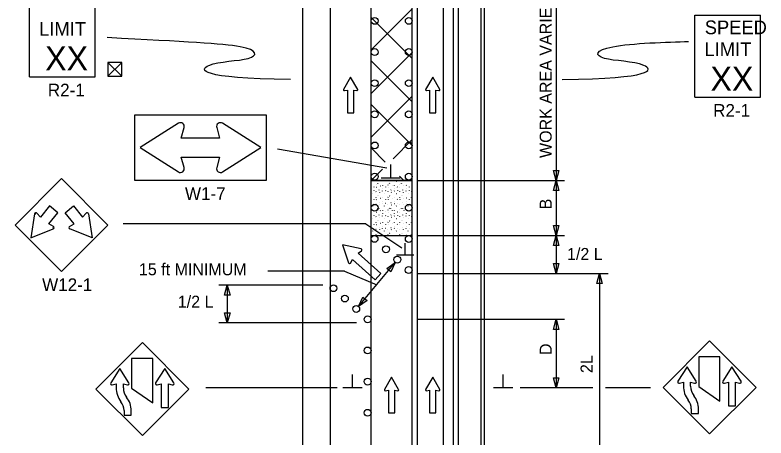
# Model space of a CAD drawing. Extents: x 16480 to 18482, y 7002 to 8333.
# Drawn here: x 16745.9 to 17184.5, y 7872.3 to 8119.6 of the extents above; entities that cross this region are included whole.
import ezdxf

# ---------------------------------------------------------------- set-up
doc = ezdxf.new("R2010")
doc.units = 0
for name, color, linetype in [('ALI_LEGAL_EX', 7, 'Continuous'), ('MT_SCRATCH_LEVEL_E', 7, 'Continuous'), ('PAVT_EDGE_EX', 7, 'Continuous'), ('TRAFFIC_SIGNS_PR', 7, 'Continuous'), ('TYPICAL_TEXT_DIMEN_PR', 7, 'Continuous')]:
    doc.layers.add(name, color=color, linetype=linetype)

msp = doc.modelspace()

# ---------------------------------------------------------------- linework, layer by layer
at = {"layer": 'ALI_LEGAL_EX'}
for p, q in [((16980.68, 8333.08), (16980.68, 7514.94)), ((17004.68, 8333.08), (17004.68, 7514.94)), ((16995.95, 8289.26), (16995.95, 7471.12)), ((17019.95, 8289.26), (17019.95, 7471.12)), ((16953.87, 7620.35), (16953.87, 8241.48)), ((16977.87, 7620.35), (16977.87, 8241.48))]:
    msp.add_line(p, q, dxfattribs=at)
for points in [[(16953.87, 8075.35), (16953.87, 8100.35)], [(16977.87, 8075.35), (16977.87, 8100.35)], [(16953.87, 7875.35), (16953.87, 7900.35)], [(16977.87, 7875.35), (16977.87, 7900.35)]]:
    msp.add_lwpolyline(points, dxfattribs=at)
at = {"layer": 'MT_SCRATCH_LEVEL_E'}
for p, q in [((16941.87, 8083.36), (16937.75, 8076.12)), ((16946.01, 8076.12), (16941.87, 8083.36)), ((16989.82, 8083.36), (16985.71, 8076.12)), ((16993.97, 8076.12), (16989.82, 8083.36)), ((16938.24, 8075.44), (16940.01, 8075.75)), ((16940.01, 8075.75), (16940.01, 8062.5)), ((16943.76, 8062.5), (16943.76, 8075.75)), ((16943.76, 8075.75), (16945.53, 8075.44)), ((16986.19, 8075.44), (16987.97, 8075.75)), ((16987.97, 8075.75), (16987.97, 8062.5)), ((16991.71, 8062.5), (16991.71, 8075.75)), ((16991.71, 8075.75), (16993.49, 8075.44)), ((16940.01, 8062.5), (16943.76, 8062.5)), ((16987.97, 8062.5), (16991.71, 8062.5)), ((16948, 7982.89), (16937.12, 7985.21)), ((16937.12, 7985.21), (16940.66, 7974.69)), ((16946.36, 7980.32), (16948.25, 7981.81)), ((16959.53, 7968.53), (16946.36, 7980.32)), ((16941.76, 7974.56), (16943.03, 7976.61)), ((16943.03, 7976.61), (16956.2, 7964.82)), ((16956.2, 7964.82), (16959.53, 7968.53)), ((16965.77, 7907.86), (16961.66, 7900.61)), ((16969.92, 7900.61), (16965.77, 7907.86)), ((16989.82, 7907.86), (16985.71, 7900.61)), ((16993.97, 7900.61), (16989.82, 7907.86)), ((16962.14, 7899.93), (16963.92, 7900.24)), ((16963.92, 7900.24), (16963.92, 7886.99)), ((16967.66, 7886.99), (16967.66, 7900.24)), ((16967.66, 7900.24), (16969.44, 7899.93)), ((16986.19, 7899.93), (16987.97, 7900.24)), ((16987.97, 7900.24), (16987.97, 7886.99)), ((16991.71, 7886.99), (16991.71, 7900.24)), ((16991.71, 7900.24), (16993.49, 7899.93)), ((16963.92, 7886.99), (16967.66, 7886.99)), ((16987.97, 7886.99), (16991.71, 7886.99))]:
    msp.add_line(p, q, dxfattribs=at)
for centre, radius, start, end in [((16938.16, 8075.9), 0.463, 150.4248, 279.9638), ((16945.6, 8075.9), 0.463, 260.0362, 29.7731), ((16986.12, 8075.9), 0.463, 150.4248, 279.9638), ((16993.56, 8075.9), 0.463, 260.0362, 29.7731), ((16947.86, 7982.29), 0.617, 308.2002, 77.9371), ((16941.24, 7974.9), 0.617, 198.5889, 328.1278), ((16962.07, 7900.39), 0.463, 150.4248, 279.9638), ((16969.51, 7900.39), 0.463, 260.0362, 29.7731), ((16986.12, 7900.39), 0.463, 150.4248, 279.9638), ((16993.56, 7900.39), 0.463, 260.0362, 29.7731)]:
    msp.add_arc(centre, radius, start, end, dxfattribs=at)
at = {"layer": 'PAVT_EDGE_EX'}
for p, q in [((16913.87, 8212.75), (16913.87, 7461.39)), ((16929.87, 8212.75), (16929.87, 7461.39)), ((17001.87, 8212.75), (17001.87, 7461.39)), ((17017.87, 8212.75), (17017.87, 7461.39)), ((16953.87, 8099.17), (16977.87, 8123.17)), ((16977.87, 8094.26), (16953.87, 8118.26)), ((16953.87, 8073.71), (16977.87, 8097.71)), ((16977.87, 8068.81), (16953.87, 8092.81)), ((16953.87, 8048.26), (16977.87, 8072.26)), ((16977.87, 8043.35), (16953.87, 8067.35)), ((16966.65, 8035.59), (16977.87, 8046.8)), ((16962.09, 8033.67), (16953.87, 8041.89)), ((16953.87, 8022.8), (16960.46, 8029.4)), ((16953.87, 8022.8), (16977.87, 8022.8)), ((16953.87, 8022.8), (16977.87, 8022.8)), ((16977.87, 8022.8), (16953.87, 8022.8)), ((16953.87, 8022.8), (16953.87, 8022.8)), ((16954.79, 8022.44), (16954.85, 8022.56)), ((16961.68, 8022.44), (16961.73, 8022.56)), ((16968.57, 8022.44), (16968.62, 8022.56)), ((16972.96, 8022.8), (16970.42, 8025.34)), ((16975.46, 8022.44), (16975.51, 8022.56)), ((16955.36, 8019.12), (16955.42, 8019.04)), ((16956.81, 8020.25), (16956.87, 8020.36)), ((16956.89, 8018.98), (16956.94, 8018.9)), ((16957.58, 8021.21), (16957.63, 8021.13)), ((16958.31, 8021.18), (16958.37, 8021.1)), ((16959.18, 8019.8), (16959.24, 8019.72)), ((16960.46, 8018.06), (16960.51, 8017.98)), ((16960.63, 8019.95), (16960.68, 8020.07)), ((16962.25, 8019.12), (16962.3, 8019.04)), ((16963.7, 8020.25), (16963.75, 8020.36)), ((16963.78, 8018.98), (16963.83, 8018.9)), ((16964.47, 8021.21), (16964.52, 8021.13)), ((16965.2, 8021.18), (16965.25, 8021.1)), ((16966.07, 8019.8), (16966.12, 8019.72)), ((16967.35, 8018.06), (16967.4, 8017.98)), ((16967.52, 8019.95), (16967.57, 8020.07)), ((16969.14, 8019.12), (16969.19, 8019.04)), ((16970.59, 8020.25), (16970.64, 8020.36)), ((16970.67, 8018.98), (16970.72, 8018.9)), ((16971.35, 8021.21), (16971.4, 8021.13)), ((16972.09, 8021.18), (16972.14, 8021.1)), ((16972.96, 8019.8), (16973.01, 8019.72)), ((16974.24, 8018.06), (16974.29, 8017.98)), ((16974.41, 8019.95), (16974.46, 8020.07)), ((16976.03, 8019.12), (16976.08, 8019.04)), ((16977.48, 8020.25), (16977.53, 8020.36)), ((16977.56, 8018.98), (16977.61, 8018.9)), ((16954.79, 8015.16), (16954.85, 8015.28)), ((16955.41, 8016.91), (16955.46, 8016.83)), ((16956.69, 8016.34), (16956.71, 8016.22)), ((16957.58, 8013.92), (16957.63, 8013.85)), ((16958.31, 8013.89), (16958.37, 8013.82)), ((16958.53, 8017.19), (16958.59, 8017.31)), ((16958.72, 8015.99), (16958.78, 8015.91)), ((16960.5, 8016.66), (16960.55, 8016.78)), ((16961.68, 8015.16), (16961.73, 8015.28)), ((16962.3, 8016.91), (16962.35, 8016.83)), ((16963.58, 8016.34), (16963.59, 8016.22)), ((16964.47, 8013.92), (16964.52, 8013.85)), ((16965.2, 8013.89), (16965.25, 8013.82)), ((16965.42, 8017.19), (16965.47, 8017.31)), ((16965.61, 8015.99), (16965.66, 8015.91)), ((16967.39, 8016.66), (16967.44, 8016.78)), ((16968.57, 8015.16), (16968.62, 8015.28)), ((16969.19, 8016.91), (16969.24, 8016.83)), ((16970.47, 8016.34), (16970.48, 8016.22)), ((16971.35, 8013.92), (16971.4, 8013.85)), ((16972.09, 8013.89), (16972.14, 8013.82)), ((16972.31, 8017.19), (16972.36, 8017.31)), ((16972.5, 8015.99), (16972.55, 8015.91)), ((16974.28, 8016.66), (16974.33, 8016.78)), ((16975.46, 8015.16), (16975.51, 8015.28)), ((16976.07, 8016.91), (16976.13, 8016.83)), ((16977.36, 8016.34), (16977.37, 8016.22)), ((16955.36, 8011.84), (16955.42, 8011.76)), ((16955.41, 8009.63), (16955.46, 8009.55)), ((16956.69, 8009.05), (16956.71, 8008.93)), ((16956.81, 8012.96), (16956.87, 8013.08)), ((16956.89, 8011.7), (16956.94, 8011.62)), ((16958.53, 8009.91), (16958.59, 8010.02)), ((16959.18, 8012.51), (16959.24, 8012.44)), ((16960.46, 8010.78), (16960.51, 8010.7)), ((16960.5, 8009.38), (16960.55, 8009.49)), ((16960.63, 8012.66), (16960.68, 8012.78)), ((16962.25, 8011.84), (16962.3, 8011.76)), ((16962.3, 8009.63), (16962.35, 8009.55)), ((16963.58, 8009.05), (16963.59, 8008.93)), ((16963.7, 8012.96), (16963.75, 8013.08)), ((16963.78, 8011.7), (16963.83, 8011.62)), ((16965.42, 8009.91), (16965.47, 8010.02)), ((16966.07, 8012.51), (16966.12, 8012.44)), ((16967.35, 8010.78), (16967.4, 8010.7)), ((16967.39, 8009.38), (16967.44, 8009.49)), ((16967.52, 8012.66), (16967.57, 8012.78)), ((16969.14, 8011.84), (16969.19, 8011.76)), ((16969.19, 8009.63), (16969.24, 8009.55)), ((16970.47, 8009.05), (16970.48, 8008.93)), ((16970.59, 8012.96), (16970.64, 8013.08)), ((16970.67, 8011.7), (16970.72, 8011.62)), ((16972.31, 8009.91), (16972.36, 8010.02)), ((16972.96, 8012.51), (16973.01, 8012.44)), ((16974.24, 8010.78), (16974.29, 8010.7)), ((16974.28, 8009.38), (16974.33, 8009.49)), ((16974.41, 8012.66), (16974.46, 8012.78)), ((16976.03, 8011.84), (16976.08, 8011.76)), ((16976.07, 8009.63), (16976.13, 8009.55)), ((16977.36, 8009.05), (16977.37, 8008.93)), ((16977.48, 8012.96), (16977.53, 8013.08)), ((16977.56, 8011.7), (16977.61, 8011.62)), ((16954.79, 8007.87), (16954.85, 8007.99)), ((16956.81, 8005.68), (16956.87, 8005.79)), ((16957.58, 8006.64), (16957.63, 8006.56)), ((16958.31, 8006.61), (16958.37, 8006.53)), ((16958.72, 8008.71), (16958.78, 8008.63)), ((16959.18, 8005.23), (16959.24, 8005.15)), ((16960.63, 8005.38), (16960.68, 8005.5)), ((16961.68, 8007.87), (16961.73, 8007.99)), ((16963.7, 8005.68), (16963.75, 8005.79)), ((16964.47, 8006.64), (16964.52, 8006.56)), ((16965.2, 8006.61), (16965.25, 8006.53)), ((16965.61, 8008.71), (16965.66, 8008.63)), ((16966.07, 8005.23), (16966.12, 8005.15)), ((16967.52, 8005.38), (16967.57, 8005.5)), ((16968.57, 8007.87), (16968.62, 8007.99)), ((16970.59, 8005.68), (16970.64, 8005.79)), ((16971.35, 8006.64), (16971.4, 8006.56)), ((16972.09, 8006.61), (16972.14, 8006.53)), ((16972.5, 8008.71), (16972.55, 8008.63)), ((16972.96, 8005.23), (16973.01, 8005.15)), ((16974.41, 8005.38), (16974.46, 8005.5)), ((16975.46, 8007.87), (16975.51, 8007.99)), ((16977.48, 8005.68), (16977.53, 8005.79)), ((16954.79, 8000.59), (16954.85, 8000.71)), ((16955.36, 8004.55), (16955.42, 8004.47)), ((16955.41, 8002.34), (16955.46, 8002.26)), ((16956.69, 8001.77), (16956.71, 8001.65)), ((16956.89, 8004.41), (16956.94, 8004.33)), ((16958.53, 8002.62), (16958.59, 8002.74)), ((16958.72, 8001.42), (16958.78, 8001.35)), ((16960.46, 8003.49), (16960.51, 8003.41)), ((16960.5, 8002.09), (16960.55, 8002.21)), ((16961.68, 8000.59), (16961.73, 8000.71)), ((16962.25, 8004.55), (16962.3, 8004.47)), ((16962.3, 8002.34), (16962.35, 8002.26)), ((16963.58, 8001.77), (16963.59, 8001.65)), ((16963.78, 8004.41), (16963.83, 8004.33)), ((16965.42, 8002.62), (16965.47, 8002.74)), ((16965.61, 8001.42), (16965.66, 8001.35)), ((16967.35, 8003.49), (16967.4, 8003.41)), ((16967.39, 8002.09), (16967.44, 8002.21)), ((16968.57, 8000.59), (16968.62, 8000.71)), ((16969.14, 8004.55), (16969.19, 8004.47)), ((16969.19, 8002.34), (16969.24, 8002.26)), ((16970.47, 8001.77), (16970.48, 8001.65)), ((16970.67, 8004.41), (16970.72, 8004.33)), ((16972.31, 8002.62), (16972.36, 8002.74)), ((16972.5, 8001.42), (16972.55, 8001.35)), ((16974.24, 8003.49), (16974.29, 8003.41)), ((16974.28, 8002.09), (16974.33, 8002.21)), ((16975.46, 8000.59), (16975.51, 8000.71)), ((16976.03, 8004.55), (16976.08, 8004.47)), ((16976.07, 8002.34), (16976.13, 8002.26)), ((16977.36, 8001.77), (16977.37, 8001.65)), ((16977.56, 8004.41), (16977.61, 8004.33)), ((16955.36, 7997.27), (16955.42, 7997.19)), ((16956.81, 7998.39), (16956.87, 7998.51)), ((16956.89, 7997.13), (16956.94, 7997.05)), ((16957.58, 7999.35), (16957.63, 7999.28)), ((16958.31, 7999.32), (16958.37, 7999.24)), ((16959.18, 7997.94), (16959.24, 7997.87)), ((16960.46, 7996.21), (16960.51, 7996.13)), ((16960.63, 7998.1), (16960.68, 7998.21)), ((16962.25, 7997.27), (16962.3, 7997.19)), ((16963.7, 7998.39), (16963.75, 7998.51)), ((16963.78, 7997.13), (16963.83, 7997.05)), ((16964.47, 7999.35), (16964.52, 7999.28)), ((16965.2, 7999.32), (16965.25, 7999.24)), ((16966.07, 7997.94), (16966.12, 7997.87)), ((16967.35, 7996.21), (16967.4, 7996.13)), ((16967.52, 7998.1), (16967.57, 7998.21)), ((16969.14, 7997.27), (16969.19, 7997.19)), ((16970.59, 7998.39), (16970.64, 7998.51)), ((16970.67, 7997.13), (16970.72, 7997.05)), ((16971.35, 7999.35), (16971.4, 7999.28)), ((16972.09, 7999.32), (16972.14, 7999.24)), ((16972.96, 7997.94), (16973.01, 7997.87)), ((16974.24, 7996.21), (16974.29, 7996.13)), ((16974.41, 7998.1), (16974.46, 7998.21)), ((16976.03, 7997.27), (16976.08, 7997.19)), ((16977.48, 7998.39), (16977.53, 7998.51)), ((16977.56, 7997.13), (16977.61, 7997.05)), ((16954.79, 7993.3), (16954.85, 7993.42)), ((16955.41, 7995.06), (16955.46, 7994.98)), ((16956.69, 7994.48), (16956.71, 7994.36)), ((16957.58, 7992.07), (16957.63, 7991.99)), ((16958.31, 7992.04), (16958.37, 7991.96)), ((16958.53, 7995.34), (16958.59, 7995.45)), ((16958.72, 7994.14), (16958.78, 7994.06)), ((16960.5, 7994.81), (16960.55, 7994.92)), ((16961.68, 7993.3), (16961.73, 7993.42)), ((16962.3, 7995.06), (16962.35, 7994.98)), ((16963.58, 7994.48), (16963.59, 7994.36)), ((16964.47, 7992.07), (16964.52, 7991.99)), ((16965.2, 7992.04), (16965.25, 7991.96)), ((16965.42, 7995.34), (16965.47, 7995.45)), ((16965.61, 7994.14), (16965.66, 7994.06)), ((16967.39, 7994.81), (16967.44, 7994.92)), ((16968.57, 7993.3), (16968.62, 7993.42)), ((16969.19, 7995.06), (16969.24, 7994.98)), ((16970.47, 7994.48), (16970.48, 7994.36)), ((16971.35, 7992.07), (16971.4, 7991.99)), ((16972.09, 7992.04), (16972.14, 7991.96)), ((16972.31, 7995.34), (16972.36, 7995.45)), ((16972.5, 7994.14), (16972.55, 7994.06)), ((16974.28, 7994.81), (16974.33, 7994.92)), ((16975.46, 7993.3), (16975.51, 7993.42)), ((16976.07, 7995.06), (16976.13, 7994.98)), ((16977.36, 7994.48), (16977.37, 7994.36)), ((16953.87, 7990.74), (16977.87, 7990.74)), ((16953.87, 7990.74), (16977.87, 7990.74)), ((16956.81, 7991.11), (16956.87, 7991.22)), ((16960.63, 7990.81), (16960.68, 7990.93)), ((16963.7, 7991.11), (16963.75, 7991.22)), ((16967.52, 7990.81), (16967.57, 7990.93)), ((16970.59, 7991.11), (16970.64, 7991.22)), ((16974.41, 7990.81), (16974.46, 7990.93)), ((16977.48, 7991.11), (16977.53, 7991.22))]:
    msp.add_line(p, q, dxfattribs=at)
at = {"layer": 'TRAFFIC_SIGNS_PR'}
for p, q in [((16754.36, 8083.47), (16754.36, 8131.47)), ((16792.76, 8083.47), (16792.76, 8131.47)), ((17142.95, 8119.54), (17181.35, 8119.54)), ((17142.95, 8071.54), (17142.95, 8119.54)), ((17181.35, 8071.54), (17181.35, 8119.54)), ((16754.36, 8083.47), (16792.76, 8083.47)), ((17142.95, 8071.54), (17181.35, 8071.54)), ((16773.02, 8023.93), (16745.87, 7996.78)), ((16800.17, 7996.78), (16773.02, 8023.93)), ((16758.11, 8003.18), (16757.34, 8003.31)), ((16745.87, 7996.78), (16773.02, 7969.63)), ((16773.02, 7969.63), (16800.17, 7996.78)), ((16767.92, 7995.31), (16768.21, 7994.56)), ((16820.23, 7928.04), (16793.08, 7900.89)), ((16847.39, 7900.89), (16820.23, 7928.04)), ((17151.51, 7929.02), (17124.36, 7901.86)), ((17178.67, 7901.86), (17151.51, 7929.02)), ((16793.08, 7900.89), (16820.23, 7873.74)), ((16820.23, 7873.74), (16847.39, 7900.89)), ((17124.36, 7901.86), (17151.51, 7874.71)), ((17151.51, 7874.71), (17178.67, 7901.86))]:
    msp.add_line(p, q, dxfattribs=at)
for points in [[(16892.57, 8022.89), (16815.77, 8022.89), (16815.77, 8061.29), (16892.57, 8061.29)], [(16813.92, 7918.82), (16813.92, 7901.48), (16826.33, 7892.86), (16826.33, 7918.82)], [(17145.2, 7919.8), (17145.2, 7902.45), (17157.61, 7893.83), (17157.61, 7919.8)]]:
    msp.add_lwpolyline(points, close=True, dxfattribs=at)
for points in [[(16841.28, 8056.29), (16818.97, 8042.09), (16841.28, 8027.88)], [(16863.69, 8053.81), (16865.36, 8047.69), (16842.97, 8047.69), (16844.65, 8053.81)], [(16867.05, 8027.89), (16889.37, 8042.09), (16867.05, 8056.29)], [(16844.65, 8030.37), (16842.97, 8036.49), (16865.36, 8036.49), (16863.69, 8030.37)], [(16768.31, 7996.01), (16765.63, 7997.44), (16770.9, 8003.99), (16765.98, 8007.96), (16760.7, 8001.4), (16758.7, 8003.7)], [(16777.74, 7996.01), (16780.41, 7997.44), (16775.14, 8003.99), (16780.06, 8007.96), (16785.34, 8001.4), (16787.35, 8003.7)], [(16757.34, 8003.31), (16755.08, 7989.42), (16768.21, 7994.56)], [(16788.71, 8003.31), (16790.96, 7989.42), (16777.83, 7994.56)], [(16812.43, 7904.6), (16807.1, 7912.96), (16801.77, 7904.59)], [(16838.65, 7904.59), (16833.33, 7912.96), (16828, 7904.59)], [(17143.71, 7905.57), (17138.38, 7913.94), (17133.05, 7905.57)], [(17169.93, 7905.57), (17164.61, 7913.94), (17159.28, 7905.57)], [(16802.7, 7903.33), (16805, 7903.96), (16804.99, 7901.73)], [(16809.19, 7901.63), (16809.19, 7903.96), (16811.49, 7903.33)], [(16828.93, 7903.33), (16831.23, 7903.96), (16831.23, 7890.16), (16835.43, 7890.16), (16835.43, 7903.96), (16837.72, 7903.33)], [(17133.98, 7904.31), (17136.28, 7904.94), (17136.28, 7902.71)], [(17140.47, 7902.6), (17140.47, 7904.94), (17142.77, 7904.31)], [(17160.21, 7904.31), (17162.51, 7904.94), (17162.51, 7891.14), (17166.71, 7891.14), (17166.71, 7904.94), (17169, 7904.31)], [(16809.56, 7888.28), (16809.56, 7885.63), (16813.76, 7885.63), (16813.76, 7888.28)], [(17140.85, 7889.25), (17140.84, 7886.6), (17145.04, 7886.6), (17145.04, 7889.25)]]:
    msp.add_lwpolyline(points, dxfattribs=at)
for centre in [(16955.97, 8116.19), (16975.84, 8116.19), (16955.97, 8097.98), (16975.84, 8097.98), (16955.97, 8079.76), (16975.84, 8079.76), (16955.97, 8061.55), (16975.84, 8061.55), (16955.97, 8043.33), (16975.84, 8043.33), (16955.97, 8025.12), (16975.84, 8025.12), (16955.97, 8006.91), (16975.84, 8006.91), (16955.85, 7988.7), (16975.84, 7988.69), (16962.5, 7982.64), (16969.15, 7976.57), (16975.8, 7970.5), (16931.86, 7959.87), (16938.51, 7953.81), (16945.16, 7947.74), (16951.8, 7941.67), (16951.8, 7941.67), (16951.8, 7923.46), (16951.8, 7905.24), (16951.8, 7887.04)]:
    msp.add_circle(centre, 2, dxfattribs=at)
for centre, radius, start, end in [((16842.49, 8054.4), 2.24, 344.6731, 122.4696), ((16865.84, 8054.4), 2.24, 57.5304, 195.3269), ((16842.49, 8029.77), 2.24, 237.5304, 15.3269), ((16865.84, 8029.78), 2.24, 164.6928, 302.4524), ((16758.11, 8003.17), 0.786, 41.8659, 170.0393), ((16787.93, 8003.17), 0.786, 9.9607, 138.1341), ((16767.92, 7995.31), 0.8, 291.4077, 61.1792), ((16778.12, 7995.31), 0.8, 118.8208, 248.5923), ((16802.48, 7904.14), 0.84, 147.5204, 285.3986), ((16811.72, 7904.14), 0.842, 254.6828, 32.2708), ((16821.28, 7910.23), 10.5, 212.4569, 212.4665), ((16828.71, 7904.14), 0.841, 147.5497, 285.3316), ((16837.94, 7904.14), 0.839, 254.6778, 32.4665), ((16847.51, 7910.23), 10.5, 212.4569, 212.4665), ((17133.76, 7905.12), 0.84, 147.5204, 285.3986), ((17143, 7905.12), 0.842, 254.6828, 32.2708), ((17140, 7894.18), 10.5, 74.68, 74.6808), ((17152.56, 7911.2), 10.5, 212.4569, 212.4665), ((17159.99, 7905.12), 0.841, 147.5497, 285.3316), ((17169.22, 7905.12), 0.839, 254.6778, 32.4665), ((17178.79, 7911.2), 10.5, 212.4569, 212.4665), ((16817.59, 7901.36), 12.59, 178.3293, 218.5427), ((16798.7, 7901.96), 10.5, 358.1894, 0.0048), ((16817.59, 7901.36), 8.4, 178.1936, 218.5465), ((16808.72, 7893.21), 10.5, 74.68, 74.6808), ((17148.87, 7902.34), 12.59, 178.3293, 218.5427), ((17129.98, 7902.94), 10.5, 358.1894, 0.0048), ((17148.87, 7902.34), 8.4, 178.1936, 218.5465), ((16801.16, 7888.28), 12.6, 0, 38.5422), ((17132.44, 7889.25), 12.6, 0, 38.5422), ((16801.16, 7888.28), 8.4, 0, 38.5457), ((17132.44, 7889.25), 8.4, 0, 38.5457)]:
    msp.add_arc(centre, radius, start, end, dxfattribs=at)
at = {"layer": 'TYPICAL_TEXT_DIMEN_PR'}
for p, q in [((17061.87, 8136.53), (17061.87, 8022.8)), ((16800.17, 8091.8), (16808.17, 8083.8)), ((16800.17, 8083.8), (16808.17, 8091.8)), ((16962.95, 8030), (16899.17, 8041.09)), ((16965.27, 8024.49), (16965.27, 8032.27)), ((17061.87, 8022.8), (17060.3, 8028.66)), ((17060.3, 8028.66), (17061.87, 8028.66)), ((17061.87, 8028.66), (17063.44, 8028.66)), ((17063.44, 8028.66), (17061.87, 8022.8)), ((16959.65, 8024.49), (16970.9, 8024.49)), ((16980.8, 8022.8), (17066.87, 8022.8)), ((17060.3, 8016.94), (17061.87, 8022.8)), ((17061.87, 8022.8), (17061.87, 7990.73)), ((17061.87, 8022.8), (17063.44, 8016.94)), ((17061.87, 8016.94), (17060.3, 8016.94)), ((17063.44, 8016.94), (17061.87, 8016.94)), ((16950.82, 7997.53), (16808.94, 7997.53)), ((16950.82, 7997.53), (16971.74, 7983.49)), ((17061.87, 7990.73), (17060.3, 7996.59)), ((17060.3, 7996.59), (17061.87, 7996.59)), ((17061.87, 7997.82), (17061.87, 7994.22)), ((17061.87, 7996.59), (17063.44, 7996.59)), ((17063.44, 7996.59), (17061.87, 7990.73)), ((16980.8, 7990.73), (17066.87, 7990.73)), ((17060.3, 7984.86), (17061.87, 7990.73)), ((17061.87, 7990.73), (17061.87, 7968.48)), ((17061.87, 7990.73), (17063.44, 7984.86)), ((16973.69, 7979.14), (16973.69, 7986.14)), ((17061.87, 7984.86), (17060.3, 7984.86)), ((17063.44, 7984.86), (17061.87, 7984.86)), ((16978.76, 7979.14), (16968.63, 7979.14)), ((16946.52, 7949.2), (16967.96, 7974.96)), ((16963.01, 7971.46), (16967.96, 7974.96)), ((16967.96, 7974.96), (16965.42, 7969.45)), ((17061.87, 7968.48), (17060.3, 7974.34)), ((17060.3, 7974.34), (17061.87, 7974.34)), ((17061.87, 7974.34), (17063.44, 7974.34)), ((17063.44, 7974.34), (17061.87, 7968.48)), ((16938.38, 7969.79), (16893.52, 7969.79)), ((16938.38, 7969.79), (16957.12, 7961.94)), ((16964.21, 7970.45), (16963.01, 7971.46)), ((16965.42, 7969.45), (16964.21, 7970.45)), ((16980.8, 7968.48), (17092.3, 7968.48)), ((17085.73, 7962.62), (17087.3, 7968.48)), ((17087.3, 7968.48), (17087.3, 7850.6)), ((17087.3, 7968.48), (17088.87, 7962.62)), ((16925.69, 7961.65), (16864.87, 7961.65)), ((16868.3, 7955.78), (16869.87, 7961.65)), ((16869.87, 7961.65), (16871.44, 7955.78)), ((16869.87, 7961.65), (16869.87, 7939.67)), ((17087.3, 7962.62), (17085.73, 7962.62)), ((17088.87, 7962.62), (17087.3, 7962.62)), ((16869.87, 7955.78), (16868.3, 7955.78)), ((16871.44, 7955.78), (16869.87, 7955.78)), ((16946.52, 7949.2), (16949.06, 7954.71)), ((16951.48, 7952.7), (16946.52, 7949.2)), ((16949.06, 7954.71), (16950.27, 7953.71)), ((16950.27, 7953.71), (16951.48, 7952.7)), ((16869.87, 7939.67), (16868.3, 7945.53)), ((16868.3, 7945.53), (16869.87, 7945.53)), ((16869.87, 7945.53), (16871.44, 7945.53)), ((16871.44, 7945.53), (16869.87, 7939.67)), ((16945.24, 7939.67), (16864.87, 7939.67)), ((16980.8, 7941.67), (17066.87, 7941.67)), ((17060.3, 7935.81), (17061.87, 7941.67)), ((17061.87, 7941.67), (17061.87, 7901.67)), ((17061.87, 7941.67), (17063.44, 7935.81)), ((17061.87, 7935.81), (17060.3, 7935.81)), ((17063.44, 7935.81), (17061.87, 7935.81)), ((16942.91, 7901.67), (16942.91, 7909.46)), ((17030.99, 7901.67), (17030.99, 7909.46)), ((17061.87, 7901.67), (17060.3, 7907.53)), ((17060.3, 7907.53), (17061.87, 7907.53)), ((17061.87, 7907.53), (17063.44, 7907.53)), ((17063.44, 7907.53), (17061.87, 7901.67)), ((16934.08, 7901.67), (16857.38, 7901.67)), ((16948.53, 7901.67), (16937.28, 7901.67)), ((17036.62, 7901.67), (17025.37, 7901.67)), ((17083.26, 7901.67), (17040.87, 7901.67)), ((17116.99, 7901.67), (17090.71, 7901.67))]:
    msp.add_line(p, q, dxfattribs=at)
msp.add_lwpolyline([(16800.17, 8091.8), (16800.17, 8083.8), (16808.17, 8083.8), (16808.17, 8091.8)], close=True, dxfattribs=at)
for points in [[(16906.7, 8081.98), (16852.93, 8082.55), (16853.59, 8092.67), (16887.82, 8092.67), (16887.82, 8102.27), (16845.96, 8103.82), (16799.67, 8106.43)], [(17065.5, 8081.98), (17119.27, 8082.55), (17118.6, 8092.67), (17084.38, 8092.67), (17084.38, 8102.34), (17127.24, 8103.86), (17139.14, 8104.12)]]:
    msp.add_open_spline(points, degree=3, dxfattribs=at)

# ---------------------------------------------------------------- texts
at = {"layer": 'TRAFFIC_SIGNS_PR'}
for s, height, p in [('LIMIT', 8, (16759.97, 8107.53)), ('SPEED', 8, (17148.72, 8108.4)), ('XX', 14.031, (16763.48, 8087.23)), ('LIMIT', 8, (17148.56, 8095.6)), ('XX', 14.031, (17152.07, 8075.3)), ('R2-1', 7.44, (16765.04, 8072.03)), ('R2-1', 7.44, (17153.63, 8060.1)), ('W1-7', 7.44, (16845.13, 8011.45)), ('W12-1', 7.44, (16761.7, 7958.19))]:
    msp.add_text(s, height=height, dxfattribs=at).set_placement(p)
at = {"layer": 'TYPICAL_TEXT_DIMEN_PR'}
for s, p in [('WORK AREA VARIES', (17059.31, 8036.02)), ('B', (17059.31, 8006)), ('D', (17059.31, 7920.79)), ('2L', (17083.17, 7910.26))]:
    msp.add_text(s, height=7, rotation=90, dxfattribs=at).set_placement(p)
for s, p in [('1/2 L', (17068.27, 7976.4)), ('15 ft MINIMUM', (16818.23, 7967.43)), ('1/2 L', (16840.94, 7948.49))]:
    msp.add_text(s, height=7, dxfattribs=at).set_placement(p)

doc.saveas('drawing.dxf')
